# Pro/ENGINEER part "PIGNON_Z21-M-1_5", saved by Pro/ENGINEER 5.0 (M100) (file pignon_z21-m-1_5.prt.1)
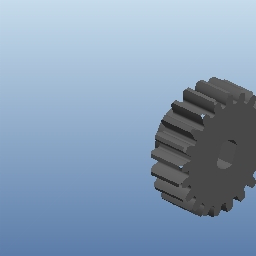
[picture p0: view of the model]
Units: millimeter Newton Second (mmNs); MM, TONNE, SECS
Materials in the file: NYLON

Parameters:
  PTC_MATERIAL_NAME = "NYLON"

Other named items: PIGNON_Z21-M-1_5

Layers: 03_PLANS, 05_SURFACES, 06_REPERES, LAYER_2682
